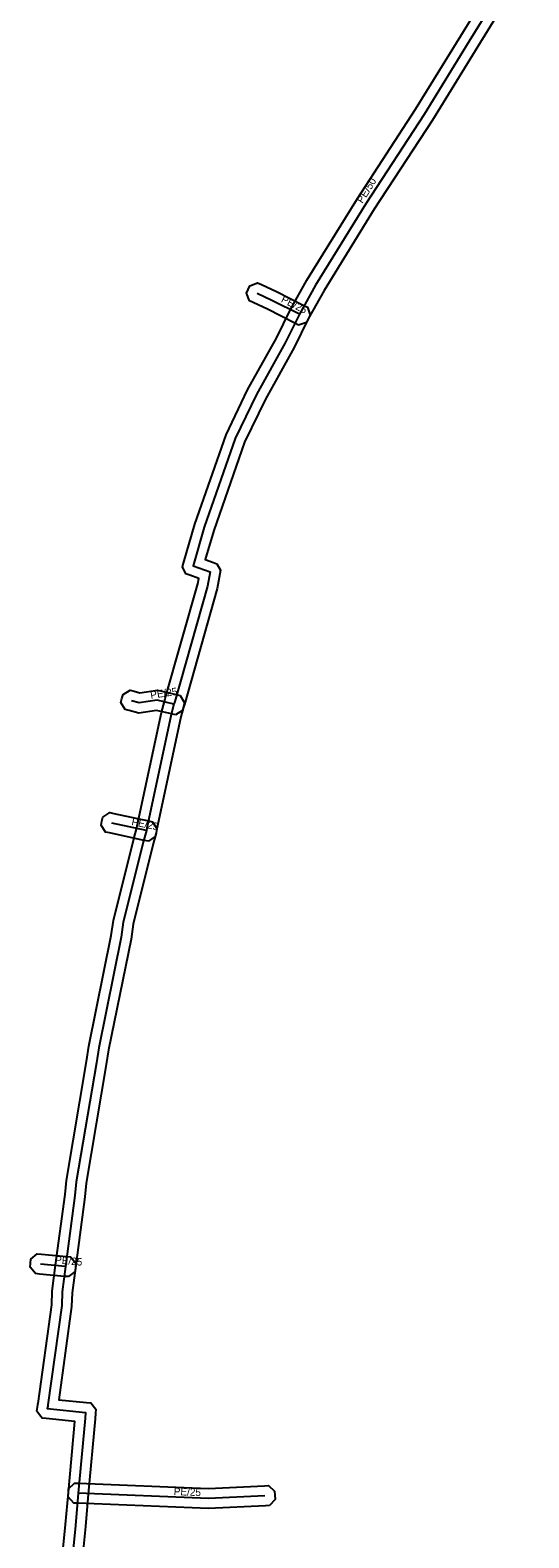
# Model space of a CAD drawing. Extents: x -681131 to -680872, y -1058347 to -1057759.
# Drawn here: x -681118.2 to -681068.2, y -1058204.3 to -1058053 of the extents above; entities that cross this region are included whole.
import ezdxf

# ---------------------------------------------------------------- set-up
doc = ezdxf.new("R2010")
doc.units = 0
for name, color, linetype in [('1', 7, 'Continuous'), ('24', 7, 'Continuous'), ('30', 7, 'Continuous')]:
    doc.layers.add(name, color=color, linetype=linetype)

msp = doc.modelspace()

# ---------------------------------------------------------------- linework, layer by layer
at = {"layer": '1'}
for points in [[(-681115.78, -1058214.01), (-681114.68, -1058202.95), (-681114.39, -1058199.72), (-681113.74, -1058192.6), (-681116.6, -1058192.31), (-681117.03, -1058192.27), (-681117.29, -1058191.93), (-681117.56, -1058191.59), (-681117.49, -1058191.16), (-681117.45, -1058190.92), (-681117.43, -1058190.81), (-681116.06, -1058180.91), (-681116.02, -1058179.53), (-681115.67, -1058176.92), (-681114.72, -1058169.84), (-681114.59, -1058168.45), (-681112.57, -1058156.48), (-681112.32, -1058154.96), (-681110.08, -1058143.87), (-681109.86, -1058142.34), (-681107.78, -1058134.02), (-681107.53, -1058133.07), (-681107.47, -1058132.87), (-681105.04, -1058121.47), (-681104.76, -1058120.37), (-681104.66, -1058120.07), (-681101.41, -1058108.59), (-681101.3, -1058108.04), (-681102.21, -1058107.72), (-681102.59, -1058107.59), (-681102.95, -1058106.88), (-681102.84, -1058106.5), (-681101.7, -1058102.6), (-681098.57, -1058093.62), (-681096.4, -1058089.12), (-681093.52, -1058083.93), (-681092.09, -1058081.07), (-681090.45, -1058078.12), (-681085.39, -1058069.92), (-681079.55, -1058060.97), (-681075.01, -1058053.6), (-681069.88, -1058045.28)], [(-681068.19, -1058046.35), (-681073.31, -1058054.66), (-681077.85, -1058062.05), (-681083.71, -1058071), (-681088.73, -1058079.14), (-681090.33, -1058082.01), (-681091.74, -1058084.87), (-681094.62, -1058090.04), (-681096.71, -1058094.38), (-681099.8, -1058103.22), (-681100.65, -1058106.15), (-681099.83, -1058106.44), (-681099.48, -1058106.56), (-681099.11, -1058107.2), (-681099.18, -1058107.56), (-681099.45, -1058109.05), (-681102.74, -1058120.67), (-681102.84, -1058120.95), (-681103.1, -1058121.93), (-681105.53, -1058133.33), (-681105.59, -1058133.58), (-681105.84, -1058134.52), (-681107.9, -1058142.72), (-681108.1, -1058144.21), (-681110.36, -1058155.32), (-681110.59, -1058156.8), (-681112.61, -1058168.71), (-681112.74, -1058170.06), (-681113.69, -1058177.18), (-681114.02, -1058179.69), (-681114.06, -1058181.07), (-681115.36, -1058190.43), (-681112.56, -1058190.71), (-681112.15, -1058190.75), (-681111.63, -1058191.38), (-681111.66, -1058191.79), (-681111.71, -1058192.35), (-681112.39, -1058199.9), (-681112.68, -1058203.13), (-681113.78, -1058214.19)]]:
    msp.add_lwpolyline(points, dxfattribs=at)
for points in [[(-681091.3, -1058082.62), (-681091.66, -1058082.43), (-681094.4, -1058081.04), (-681095.86, -1058080.37), (-681096.23, -1058080.2), (-681096.52, -1058079.42), (-681096.35, -1058079.04), (-681096.18, -1058078.67), (-681095.4, -1058078.38), (-681095.02, -1058078.55), (-681093.52, -1058079.24), (-681090.76, -1058080.65), (-681090.39, -1058080.84), (-681090.13, -1058081.62), (-681090.32, -1058081.99), (-681090.51, -1058082.36)], [(-681103.64, -1058121.73), (-681104.04, -1058121.63), (-681105.53, -1058121.27), (-681107.33, -1058121.54), (-681108.29, -1058121.29), (-681108.7, -1058121.18), (-681109.11, -1058120.47), (-681109.01, -1058120.07), (-681108.9, -1058119.67), (-681108.19, -1058119.25), (-681107.79, -1058119.35), (-681107.22, -1058119.5), (-681105.43, -1058119.23), (-681103.56, -1058119.69), (-681103.16, -1058119.79), (-681102.73, -1058120.5), (-681102.83, -1058120.9), (-681102.93, -1058121.3)], [(-681106.36, -1058134.39), (-681106.77, -1058134.31), (-681110.25, -1058133.57), (-681110.65, -1058133.48), (-681111.1, -1058132.79), (-681111.02, -1058132.38), (-681110.93, -1058131.98), (-681110.24, -1058131.53), (-681109.83, -1058131.61), (-681106.35, -1058132.35), (-681105.95, -1058132.44), (-681105.5, -1058133.13), (-681105.58, -1058133.54), (-681105.67, -1058133.94)], [(-681114.36, -1058178.08), (-681114.77, -1058178.05), (-681117.28, -1058177.82), (-681117.69, -1058177.78), (-681118.22, -1058177.14), (-681118.19, -1058176.73), (-681118.15, -1058176.32), (-681117.51, -1058175.79), (-681117.1, -1058175.82), (-681114.59, -1058176.05), (-681114.18, -1058176.09), (-681113.65, -1058176.73), (-681113.68, -1058177.14), (-681113.72, -1058177.55)], [(-681094.21, -1058201.04), (-681094.62, -1058201.06), (-681100.33, -1058201.34), (-681113.43, -1058200.81), (-681113.84, -1058200.79), (-681114.41, -1058200.18), (-681114.39, -1058199.77), (-681114.37, -1058199.35), (-681113.76, -1058198.79), (-681113.35, -1058198.81), (-681100.33, -1058199.34), (-681094.72, -1058199.06), (-681094.31, -1058199.04), (-681093.69, -1058199.6), (-681093.67, -1058200.01), (-681093.65, -1058200.42)]]:
    msp.add_lwpolyline(points, close=True, dxfattribs=at)
at = {"layer": '24'}
for points in [[(-681069.03, -1058045.82), (-681074.16, -1058054.13), (-681078.7, -1058061.51), (-681084.55, -1058070.46), (-681089.59, -1058078.63), (-681091.21, -1058081.54), (-681092.63, -1058084.4), (-681095.51, -1058089.58), (-681097.64, -1058094), (-681100.75, -1058102.91), (-681101.88, -1058106.78), (-681100.16, -1058107.38), (-681100.43, -1058108.82), (-681103.7, -1058120.37), (-681103.8, -1058120.66), (-681104.07, -1058121.7), (-681106.5, -1058133.1), (-681106.56, -1058133.33), (-681106.81, -1058134.27), (-681108.88, -1058142.53), (-681109.09, -1058144.04), (-681111.34, -1058155.14), (-681111.58, -1058156.64), (-681113.6, -1058168.58), (-681113.73, -1058169.95), (-681114.68, -1058177.05), (-681115.02, -1058179.61), (-681115.06, -1058180.99), (-681116.44, -1058190.95), (-681116.46, -1058191.07), (-681116.5, -1058191.32), (-681112.66, -1058191.7), (-681112.71, -1058192.26), (-681113.39, -1058199.81), (-681113.68, -1058203.04), (-681114.78, -1058214.1)], [(-681091.21, -1058081.54), (-681093.96, -1058080.14), (-681095.44, -1058079.46)], [(-681103.8, -1058120.66), (-681105.48, -1058120.25), (-681107.28, -1058120.52), (-681108.04, -1058120.32)], [(-681106.56, -1058133.33), (-681110.04, -1058132.59)], [(-681114.68, -1058177.05), (-681117.19, -1058176.82)], [(-681094.67, -1058200.06), (-681100.33, -1058200.34), (-681113.39, -1058199.81)]]:
    msp.add_lwpolyline(points, dxfattribs=at)

# ---------------------------------------------------------------- texts
at = {"layer": '30'}
for s, rotation, p in [('PE/50', 58.3299, (-681084.88, -1058070.47)), ('PE/25', 333.0198, (-681093.11, -1058080.27)), ('PE/25', 8.5308, (-681106.11, -1058120.12)), ('PE/25', 347.9952, (-681108.1, -1058132.76)), ('PE/25', 354.7644, (-681115.74, -1058176.74)), ('PE/25', 357.6761, (-681103.83, -1058199.99))]:
    msp.add_text(s, height=0.75, rotation=rotation, dxfattribs=at).set_placement(p)

doc.saveas('drawing.dxf')
